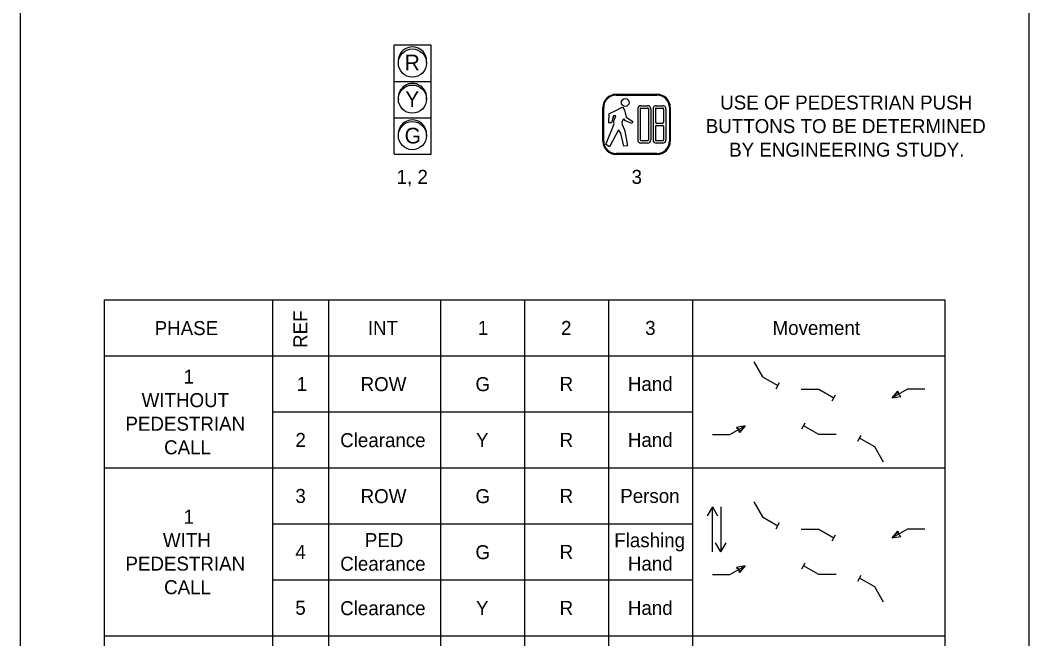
# Model space of a CAD drawing. Extents: x 515543 to 517243, y 660510 to 662861.
# Drawn here: x 516186.9 to 516636.9, y 662052.7 to 662328.9 of the extents above; entities that cross this region are included whole.
import ezdxf

# ---------------------------------------------------------------- set-up
doc = ezdxf.new("R2010")
doc.units = 0
for name, color, linetype in [('1', 7, 'Continuous'), ('Default', 7, 'Continuous'), ('RED', 7, 'Continuous'), ('TEXT', 7, 'Continuous'), ('WIRING PLAN', 7, 'Continuous'), ('YELLOW', 7, 'Continuous')]:
    doc.layers.add(name, color=color, linetype=linetype)

msp = doc.modelspace()

# ---------------------------------------------------------------- linework, layer by layer
at = {"layer": '1'}
for p, q in [((516353.71, 662317.87), (516370.02, 662317.87)), ((516353.71, 662301.56), (516353.71, 662317.87)), ((516370.02, 662317.87), (516370.02, 662301.56)), ((516353.71, 662269.17), (516353.71, 662301.56)), ((516353.71, 662301.48), (516370.02, 662301.48)), ((516370.02, 662301.56), (516370.02, 662268.94)), ((516353.71, 662285.25), (516370.02, 662285.25)), ((516370.02, 662268.94), (516353.71, 662268.94))]:
    msp.add_line(p, q, dxfattribs=at)
for centre in [(516361.87, 662309.71), (516361.87, 662293.63), (516361.87, 662277.32)]:
    msp.add_circle(centre, 6.29, dxfattribs=at)
for centre, radius, start, end in [((516361.87, 662310.61), 6.33, 353.9744, 186.0256), ((516361.87, 662294.27), 6.35, 352.1096, 187.8904), ((516361.87, 662277.99), 6.33, 353.9744, 186.0256)]:
    msp.add_arc(centre, radius, start, end, dxfattribs=at)
at = {"layer": 'Default'}
for p, q in [((516186.87, 662735.88), (516186.87, 661900.05)), ((516636.87, 662735.88), (516636.87, 661900.05)), ((516224.37, 662204), (516599.37, 662204)), ((516224.37, 662204), (516224.37, 661929)), ((516299.37, 662204), (516299.37, 661929)), ((516324.37, 662204), (516324.37, 661929)), ((516374.37, 662204), (516374.37, 661929)), ((516411.87, 662204), (516411.87, 661929)), ((516449.37, 662204), (516449.37, 662129)), ((516449.37, 662204), (516449.37, 662129)), ((516449.37, 662204), (516449.37, 661929)), ((516486.87, 662204), (516486.87, 661929)), ((516599.37, 662204), (516599.37, 661929)), ((516224.37, 662179), (516449.37, 662179)), ((516449.37, 662179), (516599.37, 662179)), ((516486.87, 662179), (516599.37, 662179)), ((516514.21, 662176.39), (516518.12, 662169.62)), ((516518.12, 662169.62), (516524.88, 662165.71)), ((516524.1, 662164.36), (516525.66, 662167.07)), ((516535.31, 662164.15), (516543.12, 662164.15)), ((516543.12, 662164.15), (516549.88, 662160.25)), ((516549.1, 662158.89), (516550.66, 662161.6)), ((516582.7, 662164.15), (516575.93, 662160.25)), ((516575.93, 662160.25), (516578.44, 662163.24)), ((516578.44, 662163.24), (516578.77, 662161.89)), ((516578.77, 662161.89), (516579.78, 662160.92)), ((516590.51, 662164.15), (516582.7, 662164.15)), ((516575.93, 662160.25), (516579.78, 662160.92)), ((516299.37, 662154), (516486.87, 662154)), ((516535.57, 662146.39), (516537.13, 662149.1)), ((516495.73, 662143.84), (516503.54, 662143.84)), ((516503.54, 662143.84), (516510.31, 662147.75)), ((516510.31, 662147.75), (516506.46, 662147.07)), ((516507.46, 662146.11), (516506.46, 662147.07)), ((516507.79, 662144.75), (516507.46, 662146.11)), ((516510.31, 662147.75), (516507.79, 662144.75)), ((516543.12, 662143.84), (516536.35, 662147.75)), ((516550.93, 662143.84), (516543.12, 662143.84)), ((516560.57, 662140.92), (516562.13, 662143.63)), ((516568.12, 662138.37), (516561.35, 662142.28)), ((516572.02, 662131.6), (516568.12, 662138.37)), ((516224.37, 662129), (516449.37, 662129)), ((516224.37, 662129), (516449.37, 662129)), ((516449.37, 662129), (516599.37, 662129)), ((516449.37, 662129), (516599.37, 662129)), ((516486.87, 662129), (516599.37, 662129)), ((516514.21, 662113.89), (516518.12, 662107.12)), ((516495.67, 662111.69), (516493.32, 662107.63)), ((516495.69, 662101.57), (516495.67, 662111.69)), ((516495.67, 662111.69), (516498.02, 662107.64)), ((516499.42, 662111.69), (516499.44, 662101.57)), ((516299.37, 662104), (516486.87, 662104)), ((516486.87, 662104), (516486.87, 662079)), ((516518.12, 662107.12), (516524.88, 662103.21)), ((516524.1, 662101.86), (516525.66, 662104.57)), ((516495.71, 662091.46), (516495.69, 662101.57)), ((516499.44, 662101.57), (516499.46, 662091.46)), ((516535.31, 662101.65), (516543.12, 662101.65)), ((516543.12, 662101.65), (516549.88, 662097.75)), ((516549.1, 662096.39), (516550.66, 662099.1)), ((516582.7, 662101.65), (516575.93, 662097.75)), ((516575.93, 662097.75), (516578.44, 662100.74)), ((516578.44, 662100.74), (516578.77, 662099.39)), ((516578.77, 662099.39), (516579.78, 662098.42)), ((516590.51, 662101.65), (516582.7, 662101.65)), ((516499.46, 662091.46), (516497.11, 662095.51)), ((516499.46, 662091.46), (516501.8, 662095.52)), ((516575.93, 662097.75), (516579.78, 662098.42)), ((516503.54, 662081.34), (516510.31, 662085.25)), ((516510.31, 662085.25), (516506.46, 662084.57)), ((516510.31, 662085.25), (516507.79, 662082.25)), ((516535.57, 662083.89), (516537.13, 662086.6)), ((516543.12, 662081.34), (516536.35, 662085.25)), ((516495.73, 662081.34), (516503.54, 662081.34)), ((516507.46, 662083.61), (516506.46, 662084.57)), ((516507.79, 662082.25), (516507.46, 662083.61)), ((516550.93, 662081.34), (516543.12, 662081.34)), ((516560.57, 662078.42), (516562.13, 662081.13)), ((516299.37, 662079), (516449.37, 662079)), ((516449.37, 662079), (516486.87, 662079)), ((516568.12, 662075.87), (516561.35, 662079.78)), ((516572.02, 662069.1), (516568.12, 662075.87)), ((516224.37, 662054), (516599.37, 662054)), ((516224.37, 662054), (516449.37, 662054)), ((516449.37, 662054), (516599.37, 662054)), ((516486.87, 662054), (516599.37, 662054))]:
    msp.add_line(p, q, dxfattribs=at)
for points in [[(516578.44, 662163.24), (516575.93, 662160.25), (516579.78, 662160.92), (516578.77, 662161.89), (516578.44, 662163.24), (516578.44, 662163.24)], [(516507.79, 662144.75), (516510.31, 662147.75), (516506.46, 662147.07), (516507.46, 662146.11), (516507.79, 662144.75), (516507.79, 662144.75)], [(516578.44, 662100.74), (516575.93, 662097.75), (516579.78, 662098.42), (516578.77, 662099.39), (516578.44, 662100.74), (516578.44, 662100.74)], [(516507.79, 662082.25), (516510.31, 662085.25), (516506.46, 662084.57), (516507.46, 662083.61), (516507.79, 662082.25), (516507.79, 662082.25)]]:
    msp.add_lwpolyline(points, dxfattribs=at)
at = {"layer": 'RED'}
for p, q in [((516452.78, 662295.78), (516470.95, 662295.78)), ((516452.78, 662295.59), (516470.95, 662295.59)), ((516452.78, 662295.4), (516470.95, 662295.4)), ((516474.99, 662289.22), (516474.99, 662275.49)), ((516476.55, 662289.81), (516476.55, 662274.9)), ((516476.73, 662289.81), (516476.73, 662274.9)), ((516476.92, 662289.81), (516476.92, 662274.9)), ((516473.95, 662281.42), (516473.95, 662275.49)), ((516470.95, 662269.31), (516452.78, 662269.31)), ((516470.95, 662269.12), (516452.78, 662269.12)), ((516470.95, 662268.94), (516452.78, 662268.94))]:
    msp.add_line(p, q, dxfattribs=at)
for centre, radius, start, end in [((516452.78, 662289.81), 5.96, 90, 180), ((516452.78, 662289.81), 5.78, 90, 180), ((516452.78, 662289.81), 5.59, 90, 180), ((516470.95, 662289.81), 5.96, 0, 90), ((516470.95, 662289.81), 5.78, 0, 90), ((516470.95, 662289.81), 5.59, 0, 90), ((516452.78, 662274.9), 5.96, 180, 270), ((516452.78, 662274.9), 5.78, 180, 270), ((516452.78, 662274.9), 5.59, 180, 270), ((516470.95, 662274.9), 5.96, 270, 0), ((516470.95, 662274.9), 5.78, 270, 0), ((516470.95, 662274.9), 5.59, 270, 0)]:
    msp.add_arc(centre, radius, start, end, dxfattribs=at)
at = {"layer": 'TEXT'}
for p, q in [((516450.13, 662287.42), (516452.59, 662288.54)), ((516452.59, 662288.54), (516454.79, 662289.8)), ((516454.79, 662289.8), (516455.25, 662290.08)), ((516455.25, 662290.08), (516455.67, 662289.92)), ((516455.67, 662289.92), (516456.08, 662289.43)), ((516456.08, 662289.43), (516456.53, 662288.66)), ((516456.53, 662288.66), (516456.79, 662287.53)), ((516456.79, 662287.53), (516457.2, 662285.53)), ((516449.53, 662287), (516449.31, 662282.96)), ((516450.63, 662283.09), (516449.31, 662282.96)), ((516449.53, 662287), (516450.13, 662287.42)), ((516451.5, 662286.19), (516450.63, 662283.09)), ((516452.55, 662286.19), (516451.5, 662286.19)), ((516451.64, 662283.7), (516451.68, 662283.9)), ((516451.65, 662283.42), (516451.64, 662283.7)), ((516451.66, 662283.16), (516451.65, 662283.42)), ((516451.72, 662282.94), (516451.66, 662283.16)), ((516451.68, 662283.9), (516452.55, 662286.19)), ((516455.6, 662284.1), (516455.23, 662283.22)), ((516455.23, 662283.22), (516455.48, 662282.29)), ((516455.9, 662284.5), (516455.6, 662284.1)), ((516456.11, 662284.75), (516455.9, 662284.5)), ((516456.91, 662283.95), (516456.11, 662284.75)), ((516459.7, 662282.74), (516456.91, 662283.95)), ((516457.2, 662285.53), (516460.13, 662283.56)), ((516460.13, 662283.56), (516459.7, 662282.74)), ((516448.11, 662273.39), (516451.87, 662282.66)), ((516453.77, 662279.9), (516449.72, 662272.38)), ((516451.87, 662282.66), (516451.72, 662282.94)), ((516454.09, 662279.47), (516453.77, 662279.9)), ((516454.53, 662278.9), (516454.09, 662279.47)), ((516454.89, 662278.45), (516454.53, 662278.9)), ((516455.48, 662282.29), (516456.3, 662280.27)), ((516456.3, 662280.27), (516456.6, 662279.33)), ((516456.6, 662279.33), (516457.77, 662272.76)), ((516456.13, 662272.55), (516454.89, 662278.45)), ((516449.72, 662272.38), (516448.11, 662273.39)), ((516457.77, 662272.76), (516456.13, 662272.55))]:
    msp.add_line(p, q, dxfattribs=at)
msp.add_circle((516456.79, 662292.11), 1.72, dxfattribs=at)
at = {"layer": 'WIRING PLAN'}
for p, q in [((516462.39, 662289.22), (516462.39, 662275.49)), ((516463.43, 662289.22), (516463.43, 662275.49)), ((516463.84, 662290.68), (516466.71, 662290.68)), ((516463.84, 662289.64), (516466.71, 662289.64)), ((516467.13, 662289.22), (516467.13, 662275.49)), ((516468.17, 662289.22), (516468.17, 662275.49)), ((516469.21, 662289.22), (516469.21, 662275.49)), ((516470.25, 662289.22), (516470.25, 662283.29)), ((516470.66, 662290.68), (516473.53, 662290.68)), ((516470.66, 662289.64), (516473.53, 662289.64)), ((516473.95, 662289.22), (516473.95, 662283.29)), ((516470.25, 662281.42), (516470.25, 662275.49)), ((516470.66, 662282.88), (516473.53, 662282.88)), ((516470.66, 662281.84), (516473.53, 662281.84)), ((516463.84, 662275.08), (516466.71, 662275.08)), ((516463.84, 662274.04), (516466.71, 662274.04)), ((516470.66, 662275.08), (516473.53, 662275.08)), ((516470.66, 662274.04), (516473.53, 662274.04))]:
    msp.add_line(p, q, dxfattribs=at)
for centre, radius, start, end in [((516463.84, 662289.22), 1.46, 90, 180), ((516463.84, 662289.22), 0.416, 90, 180), ((516466.71, 662289.22), 1.46, 0, 90), ((516466.71, 662289.22), 0.416, 0, 90), ((516470.66, 662289.22), 1.46, 90, 180), ((516470.66, 662289.22), 0.416, 90, 180), ((516473.53, 662289.22), 1.46, 0, 90), ((516473.53, 662289.22), 0.416, 0, 90), ((516470.66, 662283.29), 0.416, 180, 270), ((516473.53, 662283.29), 0.416, 270, 0), ((516470.66, 662281.42), 0.416, 90, 180), ((516473.53, 662281.42), 0.416, 0, 90), ((516463.84, 662275.49), 1.46, 180, 270), ((516463.84, 662275.49), 0.416, 180, 270), ((516466.71, 662275.49), 1.46, 270, 0), ((516466.71, 662275.49), 0.416, 270, 0), ((516470.66, 662275.49), 1.46, 180, 270), ((516470.66, 662275.49), 0.416, 180, 270), ((516473.53, 662275.49), 1.46, 270, 0), ((516473.53, 662275.49), 0.416, 270, 0)]:
    msp.add_arc(centre, radius, start, end, dxfattribs=at)
at = {"layer": 'YELLOW'}
for p, q in [((516446.82, 662274.9), (516446.82, 662289.81)), ((516447, 662274.9), (516447, 662289.81)), ((516447.19, 662274.9), (516447.19, 662289.81))]:
    msp.add_line(p, q, dxfattribs=at)

# ---------------------------------------------------------------- texts
at = {"layer": '1'}
for s, p in [('R', (516358.41, 662306.45)), ('Y', (516358.65, 662290.14)), ('G', (516358.38, 662273.83))]:
    msp.add_text(s, height=6.99, dxfattribs=at).set_placement(p)
at = {"layer": 'Default'}
for s, p in [('USE OF PEDESTRIAN PUSH ', (516499.18, 662288.98)), ('BUTTONS TO BE DETERMINED ', (516492.75, 662278.46)), ('BY ENGINEERING STUDY.', (516503.17, 662267.93)), ('1, 2', (516354.82, 662255.79)), ('3', (516459.64, 662255.79)), ('PHASE', (516246.86, 662188.27)), ('INT', (516341.97, 662188.37)), ('1', (516391.03, 662188.35)), ('2', (516428.16, 662188.35)), ('3', (516465.69, 662188.35)), ('Movement', (516522.55, 662188.37)), ('1', (516259.78, 662166.63)), ('1', (516310.24, 662163.35)), ('ROW', (516338.75, 662163.26)), ('G', (516389.99, 662163.26)), ('R', (516427.52, 662163.37)), ('Hand', (516458, 662163.37)), ('WITHOUT ', (516241.06, 662156.11)), ('PEDESTRIAN', (516233.83, 662145.59)), ('2', (516309.67, 662138.35)), ('Clearance', (516329.65, 662138.26)), ('Y', (516390.24, 662138.37)), ('R', (516427.52, 662138.37)), ('Hand', (516458, 662138.37)), ('CALL', (516251.08, 662135.06)), ('3', (516309.64, 662113.35)), ('ROW', (516338.75, 662113.26)), ('G', (516389.99, 662113.26)), ('R', (516427.52, 662113.37)), ('Person', (516454.59, 662113.37)), ('1', (516259.78, 662104.08)), ('WITH', (516250.56, 662093.66)), ('PED', (516340.62, 662093.63)), ('Flashing', (516451.91, 662093.58)), ('4', (516309.65, 662088.37)), ('G', (516389.99, 662088.26)), ('R', (516427.52, 662088.37)), ('Clearance', (516329.65, 662083.11)), ('Hand', (516458, 662083.16)), ('PEDESTRIAN', (516233.83, 662083.14)), ('CALL', (516251.08, 662072.62)), ('5', (516309.61, 662063.45)), ('Clearance', (516329.65, 662063.26)), ('Y', (516390.24, 662063.37)), ('R', (516427.52, 662063.37)), ('Hand', (516458, 662063.37))]:
    msp.add_text(s, height=6.25, dxfattribs=at).set_placement(p)
msp.add_text('REF', height=6.25, rotation=90, dxfattribs=at).set_placement((516314.99, 662182.55))

doc.saveas('drawing.dxf')
